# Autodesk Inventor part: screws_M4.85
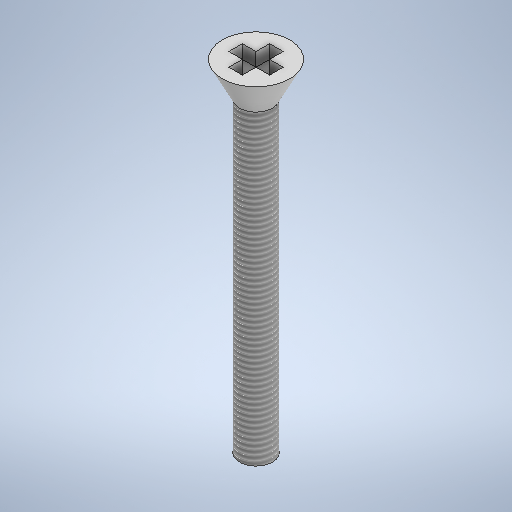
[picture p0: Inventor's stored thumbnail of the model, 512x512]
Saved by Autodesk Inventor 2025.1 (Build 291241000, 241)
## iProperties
Created: 2025-10
Part Number: screws_M4.85
Material: Genérico
Document SubType Name: Modeling
Designer: Usuario
Density: 1 g/cm^3
Appearance: Valor por defecto
Author: Usuario
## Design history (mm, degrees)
sketch "Boceto2"
  geometry: C1 r 2.425 at (0, 0); 1 further point
  constraints: 1 centre point, 1 coincident
  dimensions: "d1" = 4.85 diameter of C1 (= D_M4_85)
extrude "Extrusión1" new body sketch "Boceto2" distance "d2" = 45 (= length); taper "d3" = 0 deg
node "Plano de trabajo1"
sketch "Boceto3"
  geometry: C1 r 4.95 at (0, 0); 1 further point
  constraints: 1 centre point, 1 coincident
  dimensions: "d5" = 9.9 diameter of C1
feature "Solevación1" sketch "Boceto3" dims "d6" = 0, "d7" = 90 deg, "d8" = 0, "d9" = 90 deg
  node "Aristas1"
sketch "Boceto4"
  geometry: L1 (0, 0)-(-3, 0); L2 (-3, 0)-(3, 0); L3 (0, 0)-(0, 3); L4 (0, 3)-(0, -3); L5 (-3, 0)-(-3, 1); L6 (-3, 1)-(-3, -1); L7 (0, -3)-(-1, -3); L8 (-1, -3)-(1, -3); L9 (0, 3)-(-1, 3); L10 (-1, 3)-(1, 3); L11 (3, 0)-(3, 1); L12 (3, 1)-(3, -1); L13 (0, 0)-(0, 1); L14 (-3, 1)-(-1, 1); L15 (-1, 1)-(-1, 3); L16 (1, 3)-(1, 1); L17 (1, 1)-(3, 1); L18 (3, -1)-(1, -1); L19 (1, -1)-(1, -3); L20 (-1, -3)-(-1, -1); L21 (-1, -1)-(-3, -1); 4 further points
  constraints: 42 end point, 9 point on line, 5 horizontal, 5 perpendicular, 2 parallel, 2 vertical
  dimensions: "d14" = 1 distance of L1.end L5.end; "d15" = 2 distance of L5.end L6.end; "d18" = 1 distance of L1.start L13.end
extrude "Extrusión2" cut sketch "Boceto4" distance "d19" = 2; taper "d20" = 0 deg
feature "Rosca1" dims "d21" = 45, "d22" = 0
node "Sólido1"
other parameters: "d4" = 5, "D_M4_85" = 4.85 [user parameter; used in 1 equation term], "length" = 45 [user parameter; used in 1 equation term]
